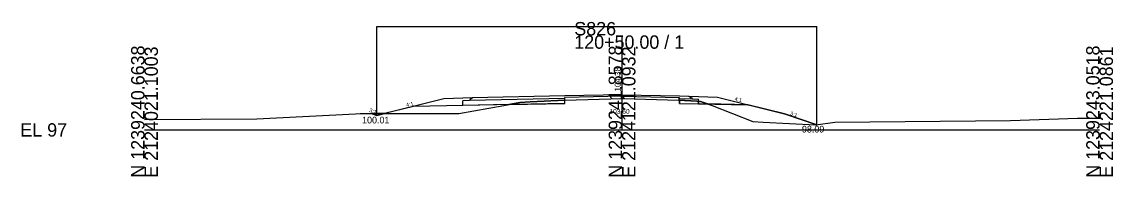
# Model space of a CAD drawing. Extents: x 2119282 to 2119710, y 1215030 to 1220057.
# Drawn here: x 2119381.9 to 2119610.4, y 1219030.1 to 1219062.5 of the extents above; entities that cross this region are included whole.
import ezdxf

# ---------------------------------------------------------------- set-up
doc = ezdxf.new("R2010")
doc.units = 0
for name, color, linetype in [('XS_CELL', 7, 'Continuous'), ('XS_M_DITCH', 7, 'Continuous'), ('XS_M_SHAPES_EARTHWORK', 7, 'Continuous'), ('XS_P_FINISHED_GRADE', 7, 'Continuous'), ('XS_P_FINISHED_GRADE_ELEV_TX', 7, 'Continuous'), ('XS_P_SUBGRADE_GRANULAR', 7, 'Continuous'), ('XS_P_SUBGRADE_PAVEMENT', 7, 'Continuous'), ('XS_P_TX_DCH', 7, 'Continuous'), ('XS_P_TX_FS_BS', 7, 'Continuous'), ('XS_X_GROUND', 7, 'Continuous'), ('XS_X_GROUND_TX', 7, 'Continuous')]:
    doc.layers.add(name, color=color, linetype=linetype)

msp = doc.modelspace()

# ---------------------------------------------------------------- linework, layer by layer
at = {"layer": 'XS_CELL'}
for p, q in [((2119507.6, 1219039.8), (2119507.6, 1219059.61)), ((2119407.6, 1219039.8), (2119507.6, 1219039.8)), ((2119507.6, 1219039.8), (2119607.6, 1219039.8))]:
    msp.add_line(p, q, dxfattribs=at)
at = {"layer": 'XS_M_DITCH'}
for p, q in [((2119456.27, 1219042.82), (2119456.27, 1219061.47)), ((2119456.27, 1219061.47), (2119548.41, 1219061.47)), ((2119548.41, 1219040.89), (2119548.41, 1219061.47))]:
    msp.add_line(p, q, dxfattribs=at)
at = {"layer": 'XS_M_SHAPES_EARTHWORK'}
for p, q in [((2119486.18, 1219045.56), (2119483.89, 1219045.12)), ((2119488.35, 1219045.66), (2119486.18, 1219045.56)), ((2119495.6, 1219046.06), (2119488.35, 1219045.66)), ((2119495.6, 1219045.36), (2119495.6, 1219046.06)), ((2119523.23, 1219045.82), (2119519.6, 1219046.03)), ((2119519.6, 1219046.03), (2119519.6, 1219045.36)), ((2119523.6, 1219045.79), (2119523.23, 1219045.82)), ((2119523.6, 1219045.28), (2119523.6, 1219045.79)), ((2119524, 1219045.76), (2119523.6, 1219045.79)), ((2119523.6, 1219045.79), (2119523.6, 1219045.28)), ((2119525.49, 1219045.24), (2119524, 1219045.76)), ((2119457.87, 1219043.22), (2119455.08, 1219043.21)), ((2119455.08, 1219043.21), (2119456.27, 1219042.82)), ((2119456.27, 1219042.82), (2119457.87, 1219043.22)), ((2119463.91, 1219044.72), (2119457.87, 1219043.22)), ((2119457.87, 1219043.22), (2119473.4, 1219043.23)), ((2119474.27, 1219044.93), (2119463.91, 1219044.72)), ((2119473.4, 1219043.23), (2119482.84, 1219044.92)), ((2119483.89, 1219045.12), (2119474.27, 1219044.93)), ((2119482.84, 1219044.92), (2119483.89, 1219045.12)), ((2119483.89, 1219045.12), (2119495.6, 1219045.36)), ((2119519.6, 1219045.36), (2119523.6, 1219045.28)), ((2119523.6, 1219045.28), (2119525.49, 1219045.24)), ((2119533.97, 1219045.07), (2119525.49, 1219045.24)), ((2119525.49, 1219045.24), (2119526.48, 1219044.89)), ((2119526.48, 1219044.89), (2119534.96, 1219041.56)), ((2119541.6, 1219043.16), (2119533.97, 1219045.07)), ((2119548.41, 1219040.89), (2119541.6, 1219043.16)), ((2119534.96, 1219041.56), (2119537.16, 1219041.41)), ((2119537.16, 1219041.41), (2119548.19, 1219040.86)), ((2119548.19, 1219040.86), (2119548.41, 1219040.89))]:
    msp.add_line(p, q, dxfattribs=at)
at = {"layer": 'XS_P_FINISHED_GRADE'}
for p, q in [((2119470.27, 1219046.32), (2119456.27, 1219042.82)), ((2119476.27, 1219046.56), (2119470.27, 1219046.32)), ((2119495.6, 1219046.94), (2119476.27, 1219046.56)), ((2119507.6, 1219047.18), (2119495.6, 1219046.94)), ((2119507.6, 1219047.18), (2119519.6, 1219046.94)), ((2119519.6, 1219046.94), (2119521.6, 1219046.9)), ((2119521.6, 1219046.9), (2119527.6, 1219046.66)), ((2119527.6, 1219046.66), (2119541.6, 1219043.16)), ((2119456.27, 1219042.82), (2119455.08, 1219043.21)), ((2119541.6, 1219043.16), (2119548.41, 1219040.89))]:
    msp.add_line(p, q, dxfattribs=at)
at = {"layer": 'XS_P_SUBGRADE_GRANULAR'}
for p, q in [((2119475.62, 1219045.96), (2119474.27, 1219045.91)), ((2119474.27, 1219044.93), (2119474.27, 1219045.91)), ((2119495.6, 1219045.36), (2119495.61, 1219046.36)), ((2119519.6, 1219045.36), (2119519.59, 1219046.36)), ((2119522.26, 1219046.31), (2119523.6, 1219046.25)), ((2119523.6, 1219045.28), (2119523.6, 1219046.25)), ((2119474.27, 1219044.93), (2119463.91, 1219044.72)), ((2119495.6, 1219045.36), (2119474.27, 1219044.93)), ((2119519.6, 1219045.36), (2119523.6, 1219045.28)), ((2119523.6, 1219045.28), (2119533.97, 1219045.07))]:
    msp.add_line(p, q, dxfattribs=at)
at = {"layer": 'XS_P_SUBGRADE_PAVEMENT'}
for p, q in [((2119495.61, 1219046.36), (2119475.62, 1219045.96)), ((2119475.77, 1219046.21), (2119475.62, 1219045.96)), ((2119476.27, 1219046.56), (2119475.77, 1219046.21)), ((2119507.6, 1219046.85), (2119495.61, 1219046.61)), ((2119495.61, 1219046.36), (2119495.61, 1219046.61)), ((2119507.6, 1219046.85), (2119519.6, 1219046.61)), ((2119519.59, 1219046.36), (2119519.6, 1219046.61)), ((2119519.59, 1219046.36), (2119522.26, 1219046.31)), ((2119521.6, 1219046.9), (2119522.11, 1219046.56)), ((2119522.11, 1219046.56), (2119522.26, 1219046.31))]:
    msp.add_line(p, q, dxfattribs=at)
at = {"layer": 'XS_X_GROUND'}
for p, q in [((2119482.84, 1219044.92), (2119486.18, 1219045.56)), ((2119486.18, 1219045.56), (2119488.35, 1219045.66)), ((2119488.35, 1219045.66), (2119495.62, 1219046.06)), ((2119495.62, 1219046.06), (2119507.6, 1219046.4)), ((2119507.6, 1219046.4), (2119507.91, 1219046.39)), ((2119507.91, 1219046.39), (2119519.39, 1219046.04)), ((2119519.39, 1219046.04), (2119523.23, 1219045.82)), ((2119523.23, 1219045.82), (2119524, 1219045.76)), ((2119524, 1219045.76), (2119526.48, 1219044.89)), ((2119431.09, 1219042.13), (2119451.76, 1219043.19)), ((2119451.76, 1219043.19), (2119452.73, 1219043.23)), ((2119452.73, 1219043.23), (2119453.13, 1219043.21)), ((2119453.13, 1219043.21), (2119473.4, 1219043.23)), ((2119473.4, 1219043.23), (2119482.84, 1219044.92)), ((2119526.48, 1219044.89), (2119534.96, 1219041.56)), ((2119407.62, 1219041.98), (2119431.09, 1219042.13)), ((2119534.96, 1219041.56), (2119537.16, 1219041.41)), ((2119537.16, 1219041.41), (2119548.19, 1219040.86)), ((2119548.19, 1219040.86), (2119552.17, 1219041.45)), ((2119552.17, 1219041.45), (2119588.97, 1219041.78)), ((2119588.97, 1219041.78), (2119602.94, 1219042.3)), ((2119602.94, 1219042.3), (2119607.62, 1219042.27))]:
    msp.add_line(p, q, dxfattribs=at)

# ---------------------------------------------------------------- texts
at = {"layer": 'XS_CELL'}
for s, p in [('S826', (2119497.6, 1219059.61)), ('120+50.00 / 1', (2119497.6, 1219056.81)), ('EL 97', (2119381.6, 1219038.4))]:
    msp.add_text(s, height=2.8, dxfattribs=at).set_placement(p)
for s, p in [('N 1239240.6638', (2119407.6, 1219029.8)), ('E 2124021.1003', (2119410.4, 1219029.8)), ('N 1239241.8578', (2119507.6, 1219029.8)), ('E 2124121.0932', (2119510.4, 1219029.8)), ('N 1239243.0518', (2119607.6, 1219029.8)), ('E 2124221.0861', (2119610.4, 1219029.8))]:
    msp.add_text(s, height=2.8, rotation=90, dxfattribs=at).set_placement(p)
at = {"layer": 'XS_P_FINISHED_GRADE_ELEV_TX'}
msp.add_text('104.38', height=1.25, rotation=90, dxfattribs=at).set_placement((2119507.3, 1219047.85))
at = {"layer": 'XS_P_TX_DCH'}
for s, p in [('100.01', (2119453.16, 1219041.16)), ('98.09', (2119545.27, 1219039.26))]:
    msp.add_text(s, height=1.4, dxfattribs=at).set_placement(p)
at = {"layer": 'XS_P_TX_FS_BS'}
for s, rotation, p in [('4:1', 14.0362, (2119462.5, 1219044.6)), ('4:1', 345.9638, (2119531.11, 1219045.96)), ('3:1', 341.5651, (2119454.59, 1219043.62)), ('3:1', 341.5651, (2119542.71, 1219042.94))]:
    msp.add_text(s, height=0.8, rotation=rotation, dxfattribs=at).set_placement(p)
at = {"layer": 'XS_X_GROUND_TX'}
msp.add_text('103.60', height=1, dxfattribs=at).set_placement((2119504.96, 1219043.18))

doc.saveas('drawing.dxf')
